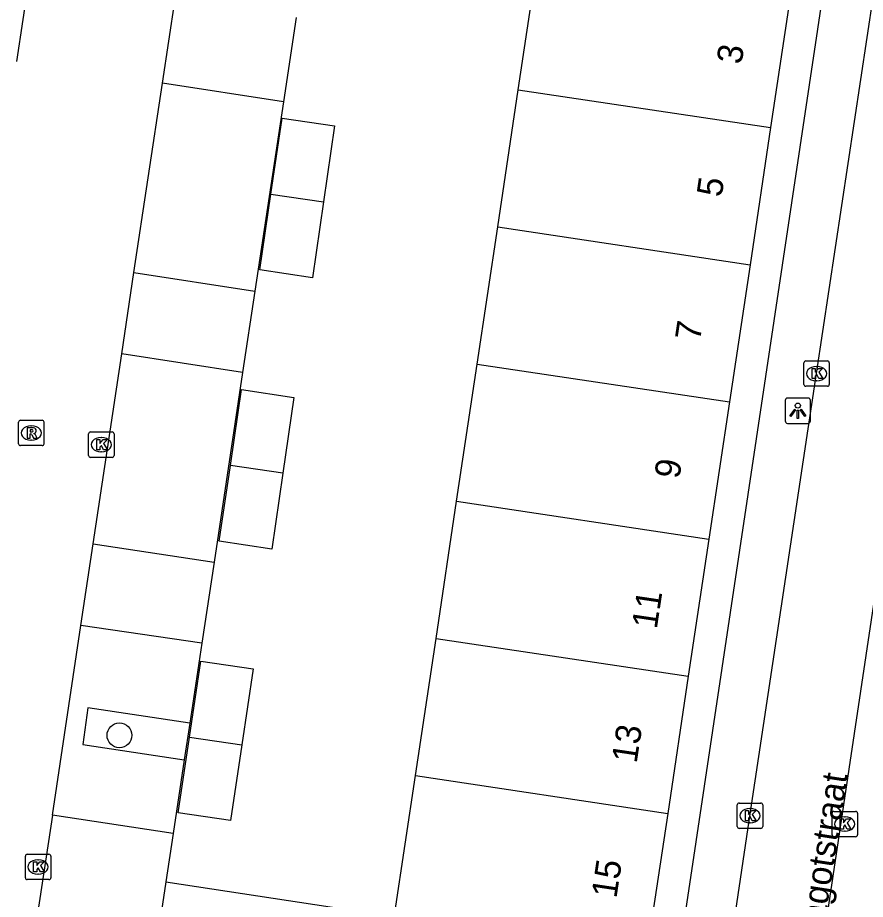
# Model space of a CAD drawing. Extents: x 164150 to 165261, y 382513 to 383432.
# Drawn here: x 164280.07 to 164313.46, y 382805.3 to 382840.05 of the extents above; entities that cross this region are included whole.
import ezdxf

# ---------------------------------------------------------------- set-up
doc = ezdxf.new("R2010")
doc.units = 0
for name, color, linetype in [('IMGEO_Boom', 7, 'Continuous'), ('IMGEO_Groenvoorziening', 7, 'Continuous'), ('IMGEO_Kolk', 7, 'Continuous'), ('IMGEO_Lichtpunt', 7, 'Continuous'), ('IMGEO_Openbare_ruimte_label', 7, 'Continuous'), ('IMGEO_Pand', 7, 'Continuous'), ('IMGEO_Pand_nummerreeks', 7, 'Continuous'), ('IMGEO_Parkeervlak_open', 7, 'Continuous'), ('IMGEO_Rijbaan_lokaal_open', 7, 'Continuous'), ('IMGEO_Rioolput', 7, 'Continuous'), ('IMGEO_Voetpad_open', 7, 'Continuous')]:
    doc.layers.add(name, color=color, linetype=linetype)

msp = doc.modelspace()

# ---------------------------------------------------------------- linework, layer by layer
at = {"layer": 'IMGEO_Boom'}
msp.add_circle((164284.082, 382811.765), 0.489, dxfattribs=at)
at = {"layer": 'IMGEO_Groenvoorziening'}
msp.add_lwpolyline([(164286.852, 382812.248), (164286.634, 382810.8)], dxfattribs=at)
at = {"layer": 'IMGEO_Kolk'}
for p, q in [((164311.04, 382825.593), (164311.04, 382826.445)), ((164311.115, 382826.519), (164311.967, 382826.519)), ((164312.041, 382826.445), (164312.041, 382825.593)), ((164311.528, 382826.299), (164311.553, 382826.299)), ((164311.967, 382825.519), (164311.115, 382825.519)), ((164311.551, 382825.739), (164311.526, 382825.739)), ((164282.942, 382823.717), (164283.794, 382823.717)), ((164282.867, 382822.791), (164282.867, 382823.643)), ((164283.355, 382823.497), (164283.38, 382823.497)), ((164283.868, 382823.643), (164283.868, 382822.791)), ((164283.794, 382822.717), (164282.942, 382822.717)), ((164283.378, 382822.937), (164283.353, 382822.937)), ((164308.491, 382809.097), (164309.343, 382809.097)), ((164308.416, 382808.171), (164308.416, 382809.023)), ((164308.904, 382808.877), (164308.929, 382808.877)), ((164309.417, 382809.023), (164309.417, 382808.171)), ((164312.225, 382808.767), (164313.077, 382808.767)), ((164312.15, 382807.841), (164312.15, 382808.693)), ((164312.638, 382808.547), (164312.663, 382808.547)), ((164313.151, 382808.693), (164313.151, 382807.841)), ((164309.343, 382808.097), (164308.491, 382808.097)), ((164308.927, 382808.317), (164308.902, 382808.317)), ((164313.077, 382807.767), (164312.225, 382807.767)), ((164312.661, 382807.987), (164312.636, 382807.987)), ((164280.378, 382806.153), (164280.378, 382807.005)), ((164280.453, 382807.079), (164281.305, 382807.079)), ((164281.379, 382807.005), (164281.379, 382806.153)), ((164280.866, 382806.859), (164280.891, 382806.859)), ((164280.889, 382806.299), (164280.864, 382806.299)), ((164281.305, 382806.079), (164280.453, 382806.079))]:
    msp.add_line(p, q, dxfattribs=at)
for points in [[(164311.04, 382825.593), (164311.04, 382826.445)], [(164311.115, 382826.519), (164311.967, 382826.519)], [(164312.041, 382826.445), (164312.041, 382825.593)], [(164311.361, 382826.219), (164311.484, 382826.219), (164311.484, 382826.068), (164311.614, 382826.219), (164311.778, 382826.219), (164311.632, 382826.068), (164311.785, 382825.819), (164311.633, 382825.819), (164311.548, 382825.983), (164311.484, 382825.916), (164311.484, 382825.819), (164311.361, 382825.819), (164311.361, 382826.219)], [(164311.967, 382825.519), (164311.115, 382825.519)], [(164282.942, 382823.717), (164283.794, 382823.717)], [(164282.867, 382822.791), (164282.867, 382823.643)], [(164283.188, 382823.417), (164283.311, 382823.417), (164283.311, 382823.266), (164283.441, 382823.417), (164283.605, 382823.417), (164283.459, 382823.266), (164283.612, 382823.017), (164283.46, 382823.017), (164283.375, 382823.181), (164283.311, 382823.114), (164283.311, 382823.017), (164283.188, 382823.017), (164283.188, 382823.417)], [(164283.868, 382823.643), (164283.868, 382822.791)], [(164283.794, 382822.717), (164282.942, 382822.717)], [(164308.491, 382809.097), (164309.343, 382809.097)], [(164308.416, 382808.171), (164308.416, 382809.023)], [(164308.737, 382808.797), (164308.86, 382808.797), (164308.86, 382808.646), (164308.99, 382808.797), (164309.154, 382808.797), (164309.008, 382808.646), (164309.161, 382808.397), (164309.009, 382808.397), (164308.924, 382808.561), (164308.86, 382808.494), (164308.86, 382808.397), (164308.737, 382808.397), (164308.737, 382808.797)], [(164309.417, 382809.023), (164309.417, 382808.171)], [(164312.225, 382808.767), (164313.077, 382808.767)], [(164312.15, 382807.841), (164312.15, 382808.693)], [(164312.471, 382808.467), (164312.594, 382808.467), (164312.594, 382808.316), (164312.724, 382808.467), (164312.888, 382808.467), (164312.742, 382808.316), (164312.895, 382808.067), (164312.743, 382808.067), (164312.658, 382808.231), (164312.594, 382808.164), (164312.594, 382808.067), (164312.471, 382808.067), (164312.471, 382808.467)], [(164313.151, 382808.693), (164313.151, 382807.841)], [(164309.343, 382808.097), (164308.491, 382808.097)], [(164313.077, 382807.767), (164312.225, 382807.767)], [(164280.378, 382806.153), (164280.378, 382807.005)], [(164280.453, 382807.079), (164281.305, 382807.079)], [(164281.379, 382807.005), (164281.379, 382806.153)], [(164280.699, 382806.779), (164280.822, 382806.779), (164280.822, 382806.628), (164280.952, 382806.779), (164281.116, 382806.779), (164280.97, 382806.628), (164281.123, 382806.379), (164280.971, 382806.379), (164280.886, 382806.543), (164280.822, 382806.476), (164280.822, 382806.379), (164280.699, 382806.379), (164280.699, 382806.779)], [(164281.305, 382806.079), (164280.453, 382806.079)]]:
    msp.add_lwpolyline(points, dxfattribs=at)
for centre, start, end in [((164311.117, 382826.443), 91.552, 178.448), ((164311.117, 382826.443), 91.552, 178.448), ((164311.965, 382826.443), 1.552, 88.448), ((164311.965, 382826.443), 1.552, 88.448), ((164311.117, 382825.595), 181.552, 268.448), ((164311.117, 382825.595), 181.552, 268.448), ((164311.965, 382825.595), 271.552, 358.448), ((164311.965, 382825.595), 271.552, 358.448), ((164282.944, 382823.641), 91.552, 178.448), ((164282.944, 382823.641), 91.552, 178.448), ((164283.792, 382823.641), 1.552, 88.448), ((164283.792, 382823.641), 1.552, 88.448), ((164282.944, 382822.793), 181.552, 268.448), ((164282.944, 382822.793), 181.552, 268.448), ((164283.792, 382822.793), 271.552, 358.448), ((164283.792, 382822.793), 271.552, 358.448), ((164308.493, 382809.021), 91.552, 178.448), ((164308.493, 382809.021), 91.552, 178.448), ((164309.341, 382809.021), 1.552, 88.448), ((164309.341, 382809.021), 1.552, 88.448), ((164312.227, 382808.691), 91.552, 178.448), ((164312.227, 382808.691), 91.552, 178.448), ((164313.075, 382808.691), 1.552, 88.448), ((164313.075, 382808.691), 1.552, 88.448), ((164308.493, 382808.173), 181.552, 268.448), ((164308.493, 382808.173), 181.552, 268.448), ((164309.341, 382808.173), 271.552, 358.448), ((164309.341, 382808.173), 271.552, 358.448), ((164312.227, 382807.843), 181.552, 268.448), ((164312.227, 382807.843), 181.552, 268.448), ((164313.075, 382807.843), 271.552, 358.448), ((164313.075, 382807.843), 271.552, 358.448), ((164280.455, 382807.003), 91.552, 178.448), ((164280.455, 382807.003), 91.552, 178.448), ((164281.303, 382807.003), 1.552, 88.448), ((164281.303, 382807.003), 1.552, 88.448), ((164280.455, 382806.155), 181.552, 268.448), ((164280.455, 382806.155), 181.552, 268.448), ((164281.303, 382806.155), 271.552, 358.448), ((164281.303, 382806.155), 271.552, 358.448)]:
    msp.add_arc(centre, 0.0765, start, end, dxfattribs=at)
for centre, major_axis, ratio, start_param, end_param in [((164311.527, 382826.019), (-0.387, 0.002), 0.722429, 4.712389, 7.853982), ((164311.552, 382826.019), (-0.39, 0.002), 0.717154, 1.570796, 4.712389), ((164283.354, 382823.217), (-0.387, 0.002), 0.722429, 4.712389, 7.853982), ((164283.379, 382823.217), (-0.39, 0.002), 0.717154, 1.570796, 4.712389), ((164308.903, 382808.597), (-0.387, 0.002), 0.722429, 4.712389, 7.853982), ((164308.928, 382808.597), (-0.39, 0.002), 0.717154, 1.570796, 4.712389), ((164312.637, 382808.267), (-0.387, 0.002), 0.722429, 4.712389, 7.853982), ((164312.662, 382808.267), (-0.39, 0.002), 0.717154, 1.570796, 4.712389), ((164280.865, 382806.579), (-0.387, 0.002), 0.722429, 4.712389, 7.853982), ((164280.89, 382806.579), (-0.39, 0.002), 0.717154, 1.570796, 4.712389)]:
    msp.add_ellipse(centre, major_axis=major_axis, ratio=ratio, start_param=start_param, end_param=end_param, dxfattribs=at)
at = {"layer": 'IMGEO_Lichtpunt'}
for p, q in [((164311.205, 382825.054), (164310.397, 382825.054)), ((164311.205, 382825.054), (164310.397, 382825.054)), ((164310.303, 382824.959), (164310.303, 382824.152)), ((164310.303, 382824.959), (164310.303, 382824.152)), ((164311.299, 382824.152), (164311.299, 382824.959)), ((164311.299, 382824.152), (164311.299, 382824.959)), ((164310.397, 382824.058), (164311.205, 382824.058)), ((164310.397, 382824.058), (164311.205, 382824.058))]:
    msp.add_line(p, q, dxfattribs=at)
for points in [[(164310.677, 382824.623), (164310.716, 382824.595), (164310.528, 382824.333), (164310.49, 382824.36), (164310.677, 382824.623)], [(164310.779, 382824.575), (164310.826, 382824.575), (164310.826, 382824.253), (164310.779, 382824.253), (164310.779, 382824.575)], [(164310.889, 382824.595), (164310.927, 382824.622), (164311.114, 382824.36), (164311.075, 382824.332), (164310.889, 382824.595)]]:
    msp.add_lwpolyline(points, dxfattribs=at)
msp.add_circle((164310.802, 382824.757), 0.0994, dxfattribs=at)
for centre, start, end in [((164310.397, 382824.959), 90, 180), ((164310.397, 382824.959), 90, 180), ((164311.205, 382824.959), 0, 90), ((164311.205, 382824.959), 0, 90), ((164310.397, 382824.152), 180, 270), ((164310.397, 382824.152), 180, 270), ((164311.205, 382824.152), 270, 0), ((164311.205, 382824.152), 270, 360)]:
    msp.add_arc(centre, 0.0946, start, end, dxfattribs=at)
at = {"layer": 'IMGEO_Pand'}
for points in [[(164299.789, 382837.204), (164300.598, 382842.61)], [(164310.54, 382841.122), (164309.73, 382835.716)], [(164298.979, 382831.798), (164299.789, 382837.204)], [(164299.789, 382837.204), (164309.73, 382835.716)], [(164290.05, 382833.094), (164290.486, 382836.082), (164292.554, 382835.786), (164292.118, 382832.792)], [(164309.73, 382835.716), (164308.919, 382830.31)], [(164292.118, 382832.792), (164291.681, 382829.797), (164289.613, 382830.106), (164290.05, 382833.094)], [(164290.05, 382833.094), (164292.118, 382832.792)], [(164298.17, 382826.393), (164298.979, 382831.798)], [(164298.979, 382831.798), (164308.919, 382830.31)], [(164308.919, 382830.31), (164308.108, 382824.905)], [(164297.361, 382820.987), (164298.17, 382826.393)], [(164298.17, 382826.393), (164308.108, 382824.905)], [(164288.452, 382822.399), (164288.891, 382825.389), (164290.952, 382825.076), (164290.516, 382822.096)], [(164308.108, 382824.905), (164307.298, 382819.499)], [(164290.516, 382822.096), (164290.079, 382819.104), (164288.013, 382819.409), (164288.452, 382822.399)], [(164290.516, 382822.096), (164288.452, 382822.399)], [(164296.551, 382815.581), (164297.361, 382820.987)], [(164297.361, 382820.987), (164307.298, 382819.499)], [(164307.298, 382819.499), (164306.487, 382814.093)], [(164295.742, 382810.175), (164296.551, 382815.581)], [(164296.551, 382815.581), (164306.487, 382814.093)], [(164286.845, 382811.698), (164287.294, 382814.687), (164289.35, 382814.385), (164288.905, 382811.388)], [(164306.487, 382814.093), (164305.677, 382808.688)], [(164288.905, 382811.388), (164288.462, 382808.404), (164286.396, 382808.708), (164286.845, 382811.698)], [(164286.845, 382811.698), (164288.905, 382811.388)], [(164305.677, 382808.688), (164304.859, 382803.235), (164294.933, 382804.769), (164295.742, 382810.175)], [(164295.742, 382810.175), (164305.677, 382808.688)]]:
    msp.add_lwpolyline(points, dxfattribs=at)
at = {"layer": 'IMGEO_Parkeervlak_open'}
for points in [[(164290.538, 382836.727), (164289.415, 382829.267)], [(164288.932, 382826.06), (164287.807, 382818.59)], [(164287.325, 382815.39), (164286.852, 382812.248)], [(164286.852, 382812.248), (164282.843, 382812.848), (164282.642, 382811.409), (164286.634, 382810.8)], [(164286.634, 382810.8), (164286.198, 382807.902)]]:
    msp.add_lwpolyline(points, dxfattribs=at)
at = {"layer": 'IMGEO_Rijbaan_lokaal_open'}
for points in [[(164301.88, 382761.702), (164302.972, 382768.762), (164306.009, 382789.028), (164308.94, 382808.745), (164311.541, 382826.019), (164314.278, 382844.244), (164317.049, 382862.672), (164317.478, 382865.636)], [(164317.721, 382843.296), (164305.588, 382762.12)], [(164280.035, 382838.315), (164280.533, 382841.634)], [(164285.773, 382837.462), (164286.273, 382840.788)], [(164284.653, 382830.001), (164285.773, 382837.462)], [(164284.171, 382826.794), (164284.653, 382830.001)], [(164283.047, 382819.316), (164284.171, 382826.794)], [(164282.562, 382816.088), (164283.047, 382819.316)], [(164281.44, 382808.615), (164282.562, 382816.088)], [(164281.44, 382808.615), (164280.584, 382802.921)]]:
    msp.add_lwpolyline(points, dxfattribs=at)
at = {"layer": 'IMGEO_Rioolput'}
for p, q in [((164280.109, 382823.254), (164280.109, 382824.106)), ((164280.184, 382824.18), (164281.036, 382824.18)), ((164281.11, 382824.106), (164281.11, 382823.254)), ((164280.597, 382823.96), (164280.622, 382823.96)), ((164280.62, 382823.4), (164280.595, 382823.4)), ((164281.036, 382823.18), (164280.184, 382823.18))]:
    msp.add_line(p, q, dxfattribs=at)
for points in [[(164280.109, 382823.254), (164280.109, 382824.106)], [(164280.184, 382824.18), (164281.036, 382824.18)], [(164281.11, 382824.106), (164281.11, 382823.254)], [(164280.698, 382823.878), (164280.446, 382823.88), (164280.446, 382823.48)], [(164280.624, 382823.799), (164280.57, 382823.799), (164280.57, 382823.718)], [(164280.57, 382823.718), (164280.622, 382823.718)], [(164280.446, 382823.48), (164280.57, 382823.48), (164280.57, 382823.642), (164280.581, 382823.642)], [(164280.628, 382823.613), (164280.699, 382823.48), (164280.839, 382823.48), (164280.774, 382823.606)], [(164281.036, 382823.18), (164280.184, 382823.18)]]:
    msp.add_lwpolyline(points, dxfattribs=at)
for centre, radius, start, end in [((164280.186, 382824.104), 0.0765, 91.552, 178.448), ((164280.186, 382824.104), 0.0765, 91.552, 178.448), ((164281.034, 382824.104), 0.0765, 1.552, 88.448), ((164281.034, 382824.104), 0.0765, 1.552, 88.448), ((164280.606, 382823.907), 0.19, 274.7715, 282.9687), ((164280.63, 382823.703), 0.0964, 77.0061, 93.1865), ((164280.644, 382823.76), 0.0378, 276.6634, 79.6772), ((164280.697, 382823.768), 0.109, 350.3612, 89.416), ((164280.695, 382823.768), 0.112, 277.5842, 350.9817), ((164280.679, 382823.553), 0.108, 29.5134, 73.7905), ((164280.58, 382823.589), 0.0533, 26.0293, 88.6989), ((164280.186, 382823.256), 0.0765, 181.552, 268.448), ((164280.186, 382823.256), 0.0765, 181.552, 268.448), ((164281.034, 382823.256), 0.0765, 271.552, 358.448), ((164281.034, 382823.256), 0.0765, 271.552, 358.448)]:
    msp.add_arc(centre, radius, start, end, dxfattribs=at)
for centre, major_axis, ratio, start_param, end_param in [((164280.596, 382823.68), (-0.387, 0.002), 0.722429, 4.712389, 7.853982), ((164280.621, 382823.68), (-0.39, 0.002), 0.717154, 1.570796, 4.712389)]:
    msp.add_ellipse(centre, major_axis=major_axis, ratio=ratio, start_param=start_param, end_param=end_param, dxfattribs=at)
at = {"layer": 'IMGEO_Voetpad_open'}
for points in [[(164306.097, 382802.914), (164312.617, 382846.453)], [(164291.038, 382840.051), (164290.538, 382836.727)], [(164290.538, 382836.727), (164285.773, 382837.462)], [(164284.653, 382830.001), (164289.415, 382829.267)], [(164289.415, 382829.267), (164288.932, 382826.06)], [(164288.932, 382826.06), (164284.171, 382826.794)], [(164283.047, 382819.316), (164287.807, 382818.59)], [(164287.807, 382818.59), (164287.325, 382815.39)], [(164287.325, 382815.39), (164282.562, 382816.088)], [(164286.198, 382807.902), (164281.44, 382808.615)], [(164286.198, 382807.902), (164285.91, 382805.985)], [(164285.91, 382805.985), (164285.646, 382804.231)], [(164285.91, 382805.985), (164306.097, 382802.914)]]:
    msp.add_lwpolyline(points, dxfattribs=at)

# ---------------------------------------------------------------- texts
at = {"layer": 'IMGEO_Openbare_ruimte_label'}
msp.add_text('Fagotstraat', height=1, rotation=81.2538, dxfattribs=at).set_placement((164311.736, 382803.518))
at = {"layer": 'IMGEO_Pand_nummerreeks'}
for s, p in [('3', (164308.582, 382838.175)), ('5', (164307.797, 382832.945)), ('7', (164306.947, 382827.276)), ('9', (164306.133, 382821.843)), ('11', (164305.245, 382815.925)), ('13', (164304.452, 382810.635)), ('15', (164303.655, 382805.317))]:
    msp.add_text(s, height=1, rotation=81.4746, dxfattribs=at).set_placement(p)

doc.saveas('drawing.dxf')
